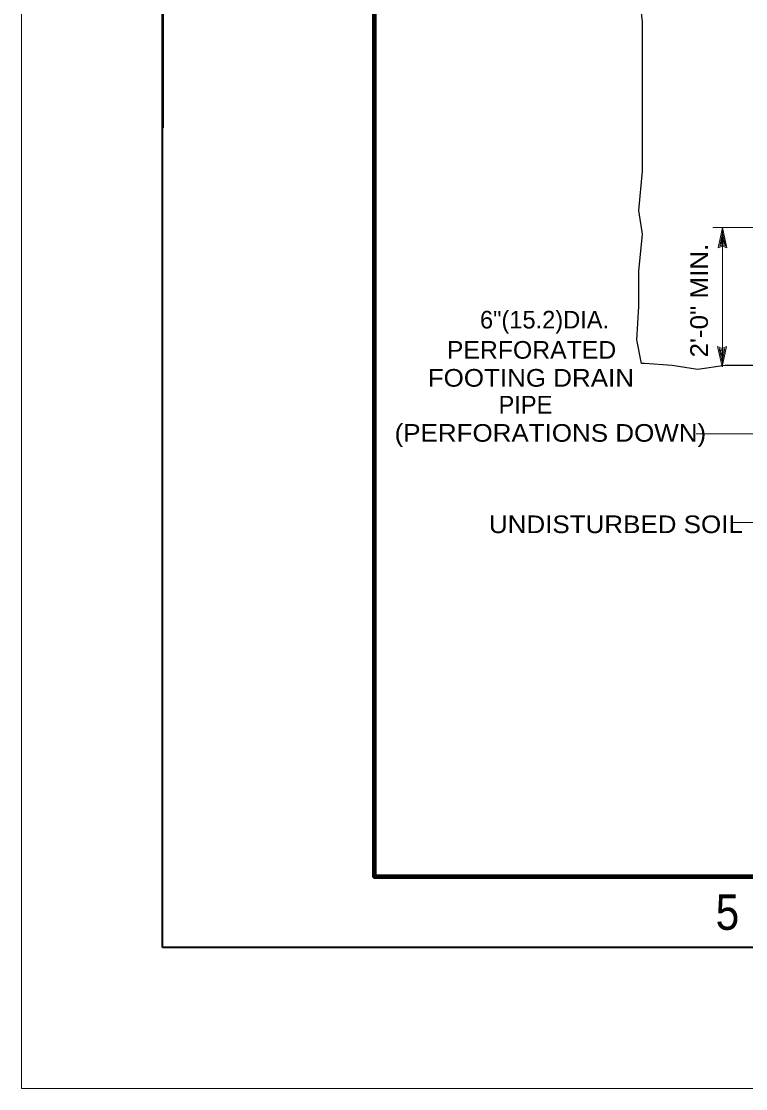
# Model space of a CAD drawing. Extents: x -24.3 to 17.7, y -17.6 to 12.4.
# Drawn here: x -24.34 to -19.21, y -17.61 to -10.05 of the extents above; entities that cross this region are included whole.
import ezdxf
from ezdxf.enums import TextEntityAlignment as Align

# ---------------------------------------------------------------- set-up
doc = ezdxf.new("R2010")
doc.units = 0
doc.header["$LTSCALE"] = 0.05
doc.layers.add('1', color=7, linetype='Continuous', lineweight=13)

msp = doc.modelspace()

# ---------------------------------------------------------------- linework, layer by layer
at = {"layer": '1'}
for p, q in [((-24.34269, -17.6106), (-24.34269, 12.3894)), ((-18.05869, -11.5136), (-19.44569, -11.5136)), ((-19.37669, -11.5136), (-19.40769, -11.6576)), ((-19.37669, -11.5506), (-19.39669, -11.6446)), ((-19.37669, -12.4996), (-19.37669, -11.5136)), ((-19.37669, -11.5136), (-19.34569, -11.6576)), ((-19.37669, -11.5506), (-19.35669, -11.6446)), ((-19.37669, -11.6356), (-19.39669, -11.6446)), ((-19.37669, -11.5866), (-19.38569, -11.6316)), ((-19.37669, -11.6276), (-19.38569, -11.6316)), ((-19.37669, -11.5866), (-19.36669, -11.6316)), ((-19.36669, -11.6316), (-19.37669, -11.6276)), ((-19.35669, -11.6446), (-19.37669, -11.6356)), ((-19.38069, -12.4996), (-19.41169, -12.3556)), ((-19.38069, -12.4626), (-19.40069, -12.3686)), ((-19.40069, -12.3686), (-19.38069, -12.3776)), ((-19.38069, -12.4266), (-19.39069, -12.3816)), ((-19.39069, -12.3816), (-19.38069, -12.3856)), ((-19.38069, -12.4996), (-19.34969, -12.3556)), ((-19.38069, -12.4626), (-19.36069, -12.3686)), ((-19.38069, -12.3776), (-19.36069, -12.3686)), ((-19.38069, -12.4266), (-19.37169, -12.3816)), ((-19.38069, -12.3856), (-19.37169, -12.3816)), ((-19.30869, -13.6016), (-18.91369, -13.6016)), ((17.65731, -17.6106), (-24.34269, -17.6106))]:
    msp.add_line(p, q, dxfattribs=at)
at = {"layer": '1', "lineweight": 40}
msp.add_line((-23.34169, -8.5556), (-23.34169, -10.8056), dxfattribs=at)
msp.add_lwpolyline([(-23.34269, -16.6106), (-23.34269, 11.3894), (16.65731, 11.3894), (16.65731, -16.6106)], close=True, dxfattribs=at)
at = {"layer": '1', "lineweight": 90}
msp.add_lwpolyline([(-21.84269, 10.8894), (16.15731, 10.8894), (16.15731, -16.1106), (-21.84269, -16.1106)], close=True, dxfattribs=at)
at = {"layer": '1', "lineweight": 25}
msp.add_lwpolyline([(-18.19969, -12.4996), (-18.44169, -12.5316), (-18.59469, -12.5316), (-18.76069, -12.5176), (-18.85869, -12.5316), (-18.96969, -12.4896), (-19.23369, -12.4896), (-19.35869, -12.4896), (-19.55369, -12.5176), (-19.73469, -12.4896), (-19.92869, -12.4756), (-19.95069, -12.4756), (-19.98469, -12.3086), (-19.97069, -12.0726), (-19.97069, -11.8226), (-19.94269, -11.5586), (-19.97069, -11.3916), (-19.94269, -11.1136), (-19.94269, -10.8626), (-19.94269, -10.7796), (-19.94269, -10.5576), (-19.94269, -10.2796), (-19.94269, -10.0566), (-19.97069, -9.8206)], dxfattribs=at)
at = {"layer": '1'}
for points in [[(-19.34569, -11.6576), (-19.37669, -11.6436), (-19.40769, -11.6576)], [(-19.56469, -12.9736), (-18.53669, -12.9736), (-17.64869, -12.1146), (-17.73069, -12.2366)], [(-19.41169, -12.3556), (-19.38069, -12.3696), (-19.34969, -12.3556)]]:
    msp.add_lwpolyline(points, dxfattribs=at)

# ---------------------------------------------------------------- texts
at = {"layer": '1', "width": 1.1}
msp.add_text('2\'-0" MIN.', height=0.125, rotation=90, dxfattribs=at).set_placement((-19.48069, -12.4326))
at = {"layer": '1'}
msp.add_text('6"(15.2)DIA.', height=0.125, dxfattribs=at).set_placement((-20.18069, -12.2276), align=Align.RIGHT)
for s, height, width, p in [('PERFORATED', 0.125, 1.05, (-20.72969, -12.4416)), ('FOOTING DRAIN', 0.125, 1.1, (-20.73419, -12.6396)), ('(PERFORATIONS DOWN)', 0.125, 1.1, (-20.59619, -13.0296)), ('UNDISTURBED SOIL', 0.125, 1.1, (-20.13219, -13.6766)), ('5', 0.25, 0.9, (-19.34219, -16.4856))]:
    msp.add_text(s, height=height, dxfattribs=dict(at, width=width)).set_placement(p, align=Align.CENTER)
msp.add_text('PIPE', height=0.125, dxfattribs=at).set_placement((-20.77269, -12.8296), align=Align.CENTER)

doc.saveas('drawing.dxf')
